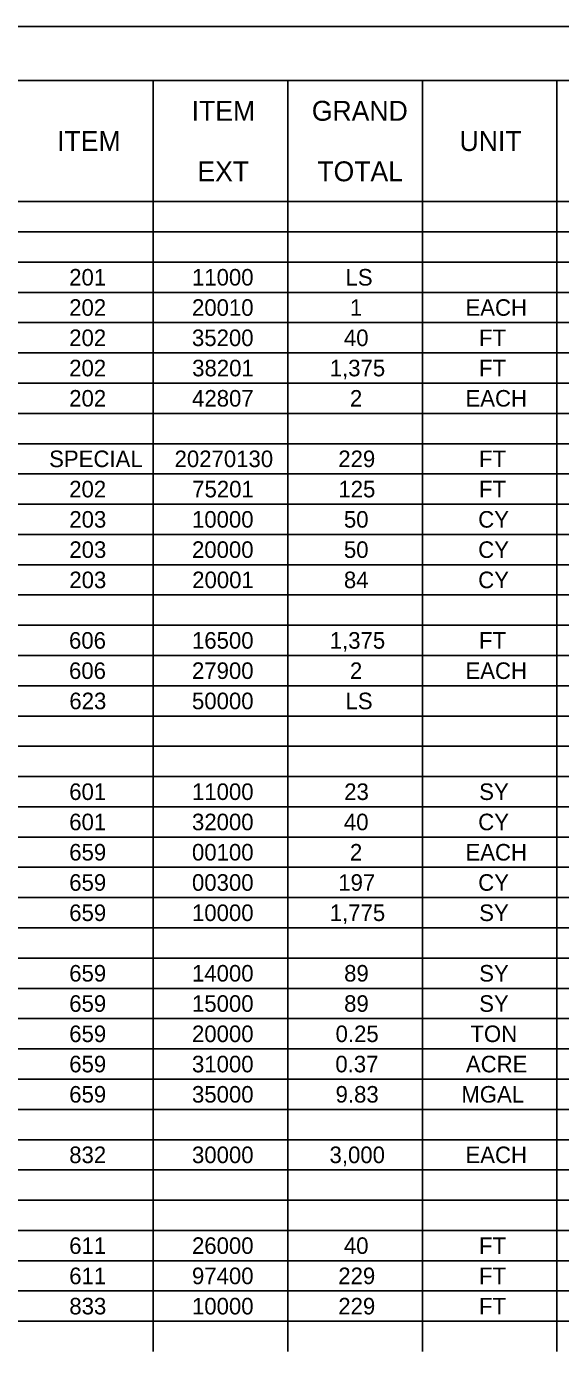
# Model space of a CAD drawing. Extents: x 0 to 34, y 0 to 22.
# Drawn here: x 9.67 to 14.61, y 9.74 to 22 of the extents above; entities that cross this region are included whole.
import ezdxf

# ---------------------------------------------------------------- set-up
doc = ezdxf.new("R2010")
doc.units = 0
for name, color, linetype in [('SH_Border', 7, 'Continuous'), ('SH_Cut_Line', 7, 'Continuous'), ('SH_Text', 7, 'Continuous')]:
    doc.layers.add(name, color=color, linetype=linetype)

msp = doc.modelspace()

# ---------------------------------------------------------------- linework, layer by layer
at = {"layer": 'SH_Border'}
msp.add_lwpolyline([(1.5, 21.5), (33.5, 21.5), (33.5, 0.5), (1.5, 0.5)], close=True, dxfattribs=at)
at = {"layer": 'SH_Cut_Line'}
msp.add_lwpolyline([(0, 0), (34, 0), (34, 22), (0, 22)], close=True, dxfattribs=at)
at = {"layer": 'SH_Text'}
for p, q in [((7.571, 21.5), (13.332, 21.5)), ((10.841, 21.5), (10.841, 21.22)), ((12.086, 21.5), (12.086, 21.22)), ((13.332, 21.5), (30.988, 21.5)), ((13.332, 21.5), (13.332, 21.22)), ((14.577, 21.5), (14.577, 21.22)), ((10.841, 21.22), (10.841, 20.94)), ((12.086, 21.22), (12.086, 20.94)), ((13.332, 21.22), (13.332, 20.94)), ((14.577, 21.22), (14.577, 20.94)), ((10.841, 20.94), (10.841, 20.66)), ((12.086, 20.94), (12.086, 20.66)), ((13.332, 20.94), (13.332, 20.66)), ((14.577, 20.94), (14.577, 20.66)), ((10.841, 20.66), (10.841, 20.38)), ((12.086, 20.66), (12.086, 20.38)), ((13.332, 20.66), (13.332, 20.38)), ((14.577, 20.66), (14.577, 20.38)), ((7.571, 20.38), (13.332, 20.38)), ((10.841, 20.38), (10.841, 20.1)), ((12.086, 20.38), (12.086, 20.1)), ((13.332, 20.38), (30.988, 20.38)), ((13.332, 20.38), (13.332, 20.1)), ((14.577, 20.38), (14.577, 20.1)), ((7.571, 20.1), (13.332, 20.1)), ((10.841, 20.1), (10.841, 18.7)), ((12.086, 20.1), (12.086, 18.7)), ((13.332, 20.1), (30.988, 20.1)), ((13.332, 20.1), (13.332, 18.7)), ((14.577, 20.1), (14.577, 18.7)), ((7.571, 19.82), (13.332, 19.82)), ((13.332, 19.82), (30.988, 19.82)), ((7.571, 19.54), (13.332, 19.54)), ((13.332, 19.54), (30.988, 19.54)), ((7.571, 19.26), (13.332, 19.26)), ((13.332, 19.26), (30.988, 19.26)), ((7.571, 18.98), (13.332, 18.98)), ((13.332, 18.98), (30.988, 18.98)), ((7.571, 18.7), (13.332, 18.7)), ((10.841, 18.7), (10.841, 18.14)), ((12.086, 18.7), (12.086, 18.14)), ((13.332, 18.7), (30.988, 18.7)), ((13.332, 18.7), (13.332, 18.14)), ((14.577, 18.7), (14.577, 18.14)), ((7.571, 18.42), (13.332, 18.42)), ((13.332, 18.42), (30.988, 18.42)), ((7.571, 18.14), (13.332, 18.14)), ((10.841, 18.14), (10.841, 17.86)), ((12.086, 18.14), (12.086, 17.86)), ((13.332, 18.14), (30.988, 18.14)), ((13.332, 18.14), (13.332, 17.86)), ((14.577, 18.14), (14.577, 17.86)), ((7.571, 17.86), (13.332, 17.86)), ((10.841, 17.86), (10.841, 17.58)), ((12.086, 17.86), (12.086, 17.58)), ((13.332, 17.86), (30.988, 17.86)), ((13.332, 17.86), (13.332, 17.58)), ((14.577, 17.86), (14.577, 17.58)), ((7.571, 17.58), (13.332, 17.58)), ((10.841, 17.58), (10.841, 17.3)), ((12.086, 17.58), (12.086, 17.3)), ((13.332, 17.58), (30.988, 17.58)), ((13.332, 17.58), (13.332, 17.3)), ((14.577, 17.58), (14.577, 17.3)), ((7.571, 17.3), (13.332, 17.3)), ((10.841, 17.3), (10.841, 17.02)), ((12.086, 17.3), (12.086, 17.02)), ((13.332, 17.3), (30.988, 17.3)), ((13.332, 17.3), (13.332, 17.02)), ((14.577, 17.3), (14.577, 17.02)), ((7.571, 17.02), (13.332, 17.02)), ((10.841, 17.02), (10.841, 16.74)), ((12.086, 17.02), (12.086, 16.74)), ((13.332, 17.02), (30.988, 17.02)), ((13.332, 17.02), (13.332, 16.74)), ((14.577, 17.02), (14.577, 16.74)), ((7.571, 16.74), (13.332, 16.74)), ((10.841, 16.74), (10.841, 16.18)), ((12.086, 16.74), (12.086, 16.18)), ((13.332, 16.74), (30.988, 16.74)), ((13.332, 16.74), (13.332, 16.18)), ((14.577, 16.74), (14.577, 16.18)), ((7.571, 16.46), (13.332, 16.46)), ((13.332, 16.46), (30.988, 16.46)), ((7.571, 16.18), (13.332, 16.18)), ((10.841, 16.18), (10.841, 15.9)), ((12.086, 16.18), (12.086, 15.9)), ((13.332, 16.18), (30.988, 16.18)), ((13.332, 16.18), (13.332, 15.9)), ((14.577, 16.18), (14.577, 15.9)), ((7.571, 15.9), (13.332, 15.9)), ((10.841, 15.9), (10.841, 15.62)), ((12.086, 15.9), (12.086, 15.62)), ((13.332, 15.9), (30.988, 15.9)), ((13.332, 15.9), (13.332, 15.62)), ((14.577, 15.9), (14.577, 15.62)), ((7.571, 15.62), (13.332, 15.62)), ((10.841, 15.62), (10.841, 15.34)), ((12.086, 15.62), (12.086, 15.34)), ((13.332, 15.62), (30.988, 15.62)), ((13.332, 15.62), (13.332, 15.34)), ((14.577, 15.62), (14.577, 15.34)), ((7.571, 15.34), (13.332, 15.34)), ((10.841, 15.34), (10.841, 14.78)), ((12.086, 15.34), (12.086, 14.78)), ((13.332, 15.34), (30.988, 15.34)), ((13.332, 15.34), (13.332, 14.78)), ((14.577, 15.34), (14.577, 14.78)), ((7.571, 15.06), (13.332, 15.06)), ((13.332, 15.06), (30.988, 15.06)), ((7.571, 14.78), (13.332, 14.78)), ((10.841, 14.78), (10.841, 14.5)), ((12.086, 14.78), (12.086, 14.5)), ((13.332, 14.78), (30.988, 14.78)), ((13.332, 14.78), (13.332, 14.5)), ((14.577, 14.78), (14.577, 14.5)), ((7.571, 14.5), (13.332, 14.5)), ((10.841, 14.5), (10.841, 14.22)), ((12.086, 14.5), (12.086, 14.22)), ((13.332, 14.5), (30.988, 14.5)), ((13.332, 14.5), (13.332, 14.22)), ((14.577, 14.5), (14.577, 14.22)), ((7.571, 14.22), (13.332, 14.22)), ((10.841, 14.22), (10.841, 13.94)), ((12.086, 14.22), (12.086, 13.94)), ((13.332, 14.22), (30.988, 14.22)), ((13.332, 14.22), (13.332, 13.94)), ((14.577, 14.22), (14.577, 13.94)), ((7.571, 13.94), (13.332, 13.94)), ((10.841, 13.94), (10.841, 11.7)), ((12.086, 13.94), (12.086, 11.7)), ((13.332, 13.94), (30.988, 13.94)), ((13.332, 13.94), (13.332, 11.7)), ((14.577, 13.94), (14.577, 11.7)), ((7.571, 13.66), (13.332, 13.66)), ((13.332, 13.66), (30.988, 13.66)), ((7.571, 13.38), (13.332, 13.38)), ((13.332, 13.38), (30.988, 13.38)), ((7.571, 13.1), (13.332, 13.1)), ((13.332, 13.1), (30.988, 13.1)), ((7.571, 12.82), (13.332, 12.82)), ((13.332, 12.82), (30.988, 12.82)), ((7.571, 12.54), (13.332, 12.54)), ((13.332, 12.54), (30.988, 12.54)), ((7.571, 12.26), (13.332, 12.26)), ((13.332, 12.26), (30.988, 12.26)), ((7.571, 11.98), (13.332, 11.98)), ((13.332, 11.98), (30.988, 11.98)), ((7.571, 11.7), (13.332, 11.7)), ((10.841, 11.7), (10.841, 11.42)), ((12.086, 11.7), (12.086, 11.42)), ((13.332, 11.7), (30.988, 11.7)), ((13.332, 11.7), (13.332, 11.42)), ((14.577, 11.7), (14.577, 11.42)), ((7.571, 11.42), (13.332, 11.42)), ((10.841, 11.42), (10.841, 10.3)), ((12.086, 11.42), (12.086, 10.3)), ((13.332, 11.42), (30.988, 11.42)), ((13.332, 11.42), (13.332, 10.3)), ((14.577, 11.42), (14.577, 10.3)), ((7.571, 11.14), (13.332, 11.14)), ((13.332, 11.14), (30.988, 11.14)), ((7.571, 10.86), (13.332, 10.86)), ((13.332, 10.86), (30.988, 10.86)), ((7.571, 10.58), (13.332, 10.58)), ((13.332, 10.58), (30.988, 10.58)), ((7.571, 10.3), (13.332, 10.3)), ((10.841, 10.3), (10.841, 10.02)), ((12.086, 10.3), (12.086, 10.02)), ((13.332, 10.3), (30.988, 10.3)), ((13.332, 10.3), (13.332, 10.02)), ((14.577, 10.3), (14.577, 10.02)), ((7.571, 10.02), (13.332, 10.02)), ((10.841, 10.02), (10.841, 9.74)), ((12.086, 10.02), (12.086, 9.74)), ((13.332, 10.02), (30.988, 10.02)), ((13.332, 10.02), (13.332, 9.74)), ((14.577, 10.02), (14.577, 9.74))]:
    msp.add_line(p, q, dxfattribs=at)

# ---------------------------------------------------------------- texts
for s, height, p in [('ITEM', 0.184, (11.196, 21.128)), ('GRAND', 0.184, (12.308, 21.128)), ('ITEM', 0.184, (9.951, 20.848)), ('UNIT', 0.184, (13.675, 20.848)), ('EXT', 0.184, (11.249, 20.568)), ('TOTAL', 0.184, (12.359, 20.568)), ('201', 0.1533, (10.063, 19.603)), ('11000', 0.1533, (11.199, 19.603)), ('LS', 0.1533, (12.62, 19.603)), ('202', 0.1533, (10.063, 19.323)), ('20010', 0.1533, (11.199, 19.323)), ('1', 0.153, (12.661, 19.323)), ('EACH', 0.1533, (13.73, 19.323)), ('202', 0.1533, (10.063, 19.043)), ('35200', 0.1533, (11.199, 19.043)), ('40', 0.1533, (12.605, 19.043)), ('FT', 0.1533, (13.855, 19.043)), ('202', 0.1533, (10.063, 18.763)), ('38201', 0.1533, (11.201, 18.763)), ('1,375', 0.1533, (12.474, 18.763)), ('FT', 0.1533, (13.855, 18.763)), ('202', 0.1533, (10.063, 18.483)), ('42807', 0.1533, (11.2, 18.483)), ('2', 0.153, (12.661, 18.483)), ('EACH', 0.1533, (13.73, 18.483)), ('SPECIAL', 0.1533, (9.877, 17.923)), ('20270130', 0.1533, (11.038, 17.923)), ('229', 0.1533, (12.553, 17.923)), ('FT', 0.1533, (13.855, 17.923)), ('202', 0.1533, (10.063, 17.643)), ('75201', 0.1533, (11.201, 17.643)), ('125', 0.1533, (12.554, 17.643)), ('FT', 0.1533, (13.855, 17.643)), ('203', 0.1533, (10.064, 17.363)), ('10000', 0.1533, (11.199, 17.363)), ('50', 0.1533, (12.605, 17.363)), ('CY', 0.1533, (13.848, 17.363)), ('203', 0.1533, (10.064, 17.083)), ('20000', 0.1533, (11.199, 17.083)), ('50', 0.1533, (12.605, 17.083)), ('CY', 0.1533, (13.848, 17.083)), ('203', 0.1533, (10.064, 16.803)), ('20001', 0.1533, (11.201, 16.803)), ('84', 0.1533, (12.605, 16.803)), ('CY', 0.1533, (13.848, 16.803)), ('606', 0.1533, (10.061, 16.243)), ('16500', 0.1533, (11.199, 16.243)), ('1,375', 0.1533, (12.474, 16.243)), ('FT', 0.1533, (13.855, 16.243)), ('606', 0.1533, (10.061, 15.963)), ('27900', 0.1533, (11.199, 15.963)), ('2', 0.153, (12.661, 15.963)), ('EACH', 0.1533, (13.73, 15.963)), ('623', 0.1533, (10.064, 15.683)), ('50000', 0.1533, (11.199, 15.683)), ('LS', 0.1533, (12.62, 15.683)), ('601', 0.1533, (10.063, 14.843)), ('11000', 0.1533, (11.199, 14.843)), ('23', 0.1533, (12.608, 14.843)), ('SY', 0.1533, (13.857, 14.843)), ('601', 0.1533, (10.063, 14.563)), ('32000', 0.1533, (11.199, 14.563)), ('40', 0.1533, (12.605, 14.563)), ('CY', 0.1533, (13.848, 14.563)), ('659', 0.1533, (10.063, 14.283)), ('00100', 0.1533, (11.199, 14.283)), ('2', 0.153, (12.661, 14.283)), ('EACH', 0.1533, (13.73, 14.283)), ('659', 0.1533, (10.063, 14.003)), ('00300', 0.1533, (11.199, 14.003)), ('197', 0.1533, (12.553, 14.003)), ('CY', 0.1533, (13.848, 14.003)), ('659', 0.1533, (10.063, 13.723)), ('10000', 0.1533, (11.199, 13.723)), ('1,775', 0.1533, (12.474, 13.723)), ('SY', 0.1533, (13.857, 13.723)), ('659', 0.1533, (10.063, 13.163)), ('14000', 0.1533, (11.199, 13.163)), ('89', 0.1533, (12.607, 13.163)), ('SY', 0.1533, (13.857, 13.163)), ('659', 0.1533, (10.063, 12.883)), ('15000', 0.1533, (11.199, 12.883)), ('89', 0.1533, (12.607, 12.883)), ('SY', 0.1533, (13.857, 12.883)), ('659', 0.1533, (10.063, 12.603)), ('20000', 0.1533, (11.199, 12.603)), ('0.25', 0.1533, (12.528, 12.603)), ('TON', 0.1533, (13.776, 12.603)), ('659', 0.1533, (10.063, 12.323)), ('31000', 0.1533, (11.199, 12.323)), ('0.37', 0.1533, (12.526, 12.323)), ('ACRE', 0.1533, (13.734, 12.323)), ('659', 0.1533, (10.063, 12.043)), ('35000', 0.1533, (11.199, 12.043)), ('9.83', 0.1533, (12.528, 12.043)), ('MGAL', 0.1533, (13.692, 12.043)), ('832', 0.1533, (10.063, 11.483)), ('30000', 0.1533, (11.199, 11.483)), ('3,000', 0.1533, (12.472, 11.483)), ('EACH', 0.1533, (13.73, 11.483)), ('611', 0.1533, (10.063, 10.643)), ('26000', 0.1533, (11.199, 10.643)), ('40', 0.1533, (12.605, 10.643)), ('FT', 0.1533, (13.855, 10.643)), ('611', 0.1533, (10.063, 10.363)), ('97400', 0.1533, (11.199, 10.363)), ('229', 0.1533, (12.553, 10.363)), ('FT', 0.1533, (13.855, 10.363)), ('833', 0.1533, (10.064, 10.083)), ('10000', 0.1533, (11.199, 10.083)), ('229', 0.1533, (12.553, 10.083)), ('FT', 0.1533, (13.855, 10.083))]:
    msp.add_text(s, height=height, dxfattribs=at).set_placement(p)

doc.saveas('drawing.dxf')
